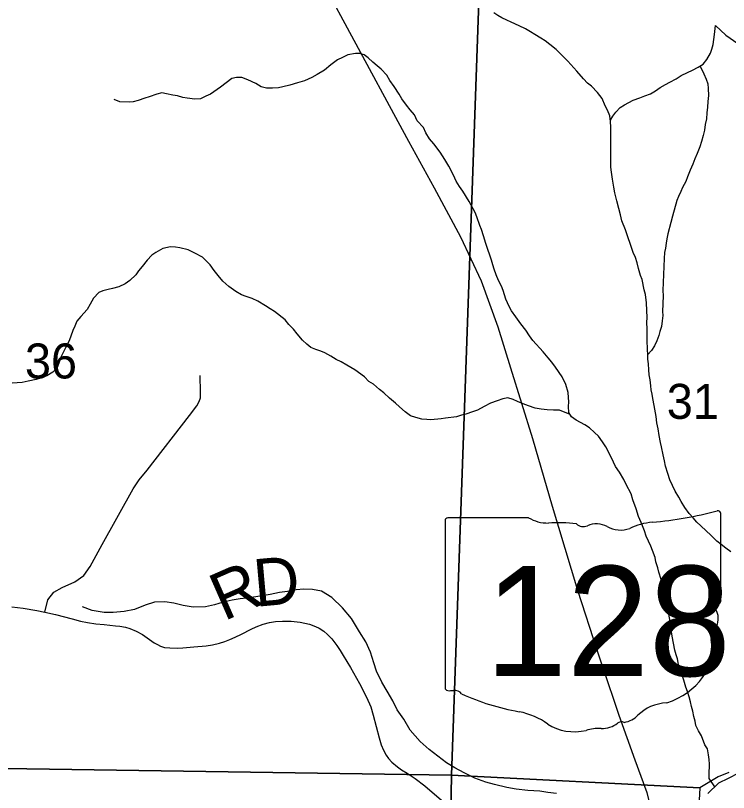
# Model space of a CAD drawing. Extents: x 0 to 34, y 0 to 22.
# Drawn here: x 3.401 to 4.254, y 17.776 to 18.706 of the extents above; entities that cross this region are included whole.
import ezdxf

# ---------------------------------------------------------------- set-up
doc = ezdxf.new("R2010")
doc.units = 0
for name, color, linetype in [('GM_X_County_Road', 7, 'Continuous'), ('GM_X_County_Road_Text', 7, 'Continuous'), ('GM_X_Major_River', 7, 'Continuous'), ('GM_X_Minor_River', 7, 'Continuous'), ('GM_X_Section', 7, 'Continuous'), ('GM_X_Section_Text', 7, 'Continuous'), ('GM_X_State_Location', 7, 'Continuous'), ('GM_X_State_Route', 7, 'Continuous'), ('GM_X_State_Shield', 7, 'Continuous'), ('GM_X_Township_Road', 7, 'Continuous')]:
    doc.layers.add(name, color=color, linetype=linetype)

msp = doc.modelspace()

# ---------------------------------------------------------------- linework, layer by layer
at = {"layer": 'GM_X_County_Road'}
msp.add_lwpolyline([(3.39721, 17.99822), (3.41074, 17.99624), (3.42685, 17.9937), (3.43662, 17.99179), (3.4494, 17.98866), (3.46903, 17.98358), (3.479, 17.98101), (3.48771, 17.97928), (3.49743, 17.97787), (3.50765, 17.97689), (3.52102, 17.97546), (3.52626, 17.97501), (3.53298, 17.97376), (3.53828, 17.97213), (3.5459, 17.96894), (3.5532, 17.96485), (3.56721, 17.95507), (3.57119, 17.95282), (3.57509, 17.95093), (3.57964, 17.94949), (3.58594, 17.94878), (3.59475, 17.94869), (3.60179, 17.94906), (3.61496, 17.95003), (3.6297, 17.9515), (3.63719, 17.95263), (3.6453, 17.95461), (3.65171, 17.95668), (3.65796, 17.95895), (3.66422, 17.96172), (3.67187, 17.96528), (3.68334, 17.97134), (3.68943, 17.97427), (3.69792, 17.97744), (3.70531, 17.97928), (3.71246, 17.98037), (3.72075, 17.981), (3.73119, 17.98076), (3.74219, 17.97969), (3.753, 17.97741), (3.76039, 17.97455), (3.76488, 17.97232), (3.77024, 17.96876), (3.77473, 17.96501), (3.77993, 17.95973), (3.78583, 17.95181), (3.78979, 17.94585), (3.79362, 17.93975), (3.80218, 17.92536), (3.81287, 17.9064), (3.8214, 17.88992), (3.82642, 17.8782), (3.82948, 17.86836), (3.83652, 17.84119), (3.83893, 17.83292), (3.8416, 17.82654), (3.84492, 17.82041), (3.84769, 17.81648), (3.85182, 17.81214), (3.8584, 17.80641), (3.86332, 17.80301), (3.87, 17.79882), (3.87945, 17.79246), (3.89098, 17.78361), (3.91371, 17.76432)], dxfattribs=at)
at = {"layer": 'GM_X_Major_River'}
msp.add_lwpolyline([(4.26631, 17.79912), (4.25396, 17.79266), (4.24239, 17.78694), (4.22985, 17.77441)], dxfattribs=at)
at = {"layer": 'GM_X_Minor_River'}
for points in [[(4.25715, 18.06375), (4.25122, 18.06814), (4.24568, 18.07251), (4.2405, 18.07649), (4.23317, 18.08396), (4.22765, 18.08909), (4.2214, 18.09501), (4.21661, 18.09935), (4.21223, 18.10445), (4.20749, 18.10993), (4.20242, 18.11694), (4.19774, 18.12432), (4.19487, 18.12936), (4.19056, 18.13635), (4.1842, 18.15025), (4.1818, 18.15756), (4.17907, 18.16639), (4.17777, 18.1729), (4.17613, 18.18017), (4.17418, 18.18974), (4.17321, 18.19472), (4.17161, 18.20313), (4.17036, 18.21116), (4.16872, 18.21843), (4.16783, 18.22569), (4.16563, 18.23906), (4.16403, 18.24748), (4.16306, 18.25245), (4.1621, 18.25781), (4.16152, 18.26277), (4.16062, 18.26964), (4.15969, 18.27575), (4.15914, 18.28185), (4.15863, 18.28909), (4.15806, 18.29443), (4.15785, 18.29938), (4.15773, 18.30698), (4.1573, 18.3165), (4.1572, 18.32448), (4.15704, 18.33095), (4.15692, 18.33855), (4.15712, 18.34424), (4.15665, 18.35262), (4.15621, 18.36176), (4.15504, 18.37206), (4.15371, 18.37742), (4.1511, 18.38968), (4.14937, 18.39468), (4.14663, 18.40313), (4.14533, 18.40964), (4.14328, 18.41617), (4.14046, 18.42235), (4.13737, 18.43196), (4.13388, 18.44081), (4.13114, 18.44927), (4.12695, 18.46006), (4.12531, 18.46733), (4.1233, 18.475), (4.12096, 18.48421), (4.11863, 18.49379), (4.11734, 18.50029), (4.11577, 18.50985), (4.11454, 18.51825), (4.11361, 18.52436), (4.11352, 18.53273), (4.11384, 18.54184), (4.1138, 18.55172), (4.11364, 18.55819), (4.11353, 18.56579), (4.11375, 18.57224), (4.11323, 18.5791), (4.11231, 18.5856), (4.10989, 18.59252), (4.10704, 18.59794), (4.10316, 18.60643), (4.09772, 18.61384), (4.09077, 18.6213), (4.08596, 18.62489), (4.0812, 18.62999), (4.07317, 18.63939), (4.06219, 18.65117), (4.05522, 18.65825), (4.04825, 18.66533), (4.04086, 18.67129), (4.03494, 18.67567), (4.03011, 18.67888), (4.02268, 18.68332), (4.01747, 18.68654), (4.01151, 18.68979), (4.00404, 18.69346), (3.99433, 18.69798), (3.9891, 18.70044), (3.98349, 18.70292), (3.97865, 18.70574), (3.97383, 18.70895)], [(4.23756, 18.68312), (4.23895, 18.69396), (4.25115, 18.68221), (4.26567, 18.67229), (4.28066, 18.66503), (4.29443, 18.65551), (4.30735, 18.6426), (4.31883, 18.63239), (4.32872, 18.61994), (4.33935, 18.60672), (4.3512, 18.59612), (4.35735, 18.5853), (4.36493, 18.57178)], [(4.11287, 18.58163), (4.11328, 18.58062), (4.1161, 18.58546), (4.11969, 18.59028), (4.12481, 18.5958), (4.13024, 18.59904), (4.13528, 18.6019), (4.1403, 18.60439), (4.14838, 18.60753), (4.15453, 18.6096), (4.16106, 18.61203), (4.16726, 18.61562), (4.17272, 18.61961), (4.17929, 18.62318), (4.18433, 18.62605), (4.19168, 18.62998), (4.19789, 18.63394), (4.2056, 18.63748), (4.2114, 18.64032), (4.21835, 18.64388), (4.22417, 18.64748), (4.22856, 18.65341), (4.23299, 18.66086), (4.23468, 18.66574), (4.236, 18.67101), (4.23697, 18.67706), (4.23756, 18.68312)], [(3.95151, 18.46992), (3.94438, 18.48309), (3.93645, 18.49552), (3.93248, 18.50136), (3.92852, 18.50758), (3.92535, 18.51491), (3.92003, 18.52573), (3.91499, 18.53351), (3.9096, 18.54243), (3.90196, 18.5522), (3.89685, 18.55808), (3.89255, 18.56545), (3.88974, 18.572), (3.88204, 18.57987), (3.87886, 18.58682), (3.87377, 18.59308), (3.8694, 18.59855), (3.86358, 18.60597), (3.86037, 18.61178), (3.8546, 18.62072), (3.84916, 18.62813), (3.84558, 18.63434), (3.839, 18.64178), (3.8342, 18.64575), (3.82904, 18.65011), (3.82352, 18.65524), (3.81871, 18.65883), (3.81345, 18.66053), (3.80813, 18.66034), (3.79897, 18.65875), (3.79278, 18.65554), (3.78661, 18.65272), (3.77881, 18.64691), (3.77099, 18.64034), (3.76247, 18.63531), (3.75589, 18.63174), (3.74702, 18.62786), (3.73895, 18.6251), (3.72975, 18.62238), (3.72133, 18.62039), (3.71598, 18.61944), (3.70875, 18.61893), (3.70153, 18.6188), (3.69552, 18.62053), (3.68882, 18.62456), (3.67948, 18.62906), (3.67236, 18.63159), (3.66591, 18.63181), (3.66017, 18.63049), (3.65354, 18.6254), (3.64652, 18.61994), (3.63484, 18.6116), (3.62907, 18.60952), (3.62289, 18.60632), (3.61604, 18.60579), (3.60696, 18.60687), (3.60168, 18.60781), (3.59528, 18.60955), (3.58962, 18.61051), (3.58209, 18.61229), (3.57643, 18.61325), (3.57067, 18.61154), (3.56145, 18.60844), (3.55609, 18.60711), (3.54801, 18.60397), (3.54227, 18.60265), (3.53732, 18.60206), (3.52632, 18.60244), (3.51959, 18.60533)], [(4.22055, 18.64524), (4.22492, 18.63605), (4.22774, 18.62987), (4.22982, 18.6241), (4.23, 18.61839), (4.23047, 18.61002), (4.22984, 18.60282), (4.22923, 18.596), (4.22863, 18.58956), (4.228, 18.58236), (4.22662, 18.57557), (4.22563, 18.56876), (4.22427, 18.56235), (4.22212, 18.5552), (4.22, 18.54881), (4.21706, 18.54055), (4.21418, 18.53419), (4.21168, 18.52782), (4.20878, 18.5207), (4.20547, 18.51283), (4.20338, 18.5072), (4.19934, 18.50012), (4.19727, 18.49525), (4.19478, 18.48926), (4.19272, 18.48439), (4.18751, 18.46557), (4.18535, 18.45804), (4.18185, 18.44448), (4.18088, 18.43843), (4.17995, 18.43353), (4.17898, 18.42748), (4.17804, 18.42219), (4.17741, 18.41499), (4.17608, 18.37665), (4.17624, 18.37019), (4.1756, 18.35159), (4.17581, 18.34664), (4.17522, 18.34058), (4.17422, 18.33377), (4.1725, 18.32775), (4.17119, 18.32286), (4.16869, 18.31648), (4.16582, 18.3105), (4.16221, 18.30492), (4.15784, 18.29998)], [(4.23812, 17.78267), (4.23145, 17.79254), (4.23124, 17.79749), (4.23166, 17.80964), (4.23148, 17.81534), (4.23052, 17.8207), (4.22925, 17.82796), (4.22601, 17.83301), (4.22221, 17.84378), (4.21861, 17.84961), (4.21541, 17.8558), (4.21446, 17.86115), (4.21314, 17.8669), (4.21183, 17.87302), (4.21013, 17.87878), (4.20917, 17.88414), (4.20749, 17.89027), (4.20544, 17.8968), (4.20333, 17.90182), (4.20097, 17.91026), (4.19858, 17.91794), (4.19651, 17.92409), (4.19478, 17.92909), (4.19349, 17.9356), (4.19177, 17.9406), (4.19045, 17.94635), (4.18882, 17.95438), (4.18722, 17.9628), (4.18567, 17.97311), (4.1851, 17.97845), (4.18288, 17.99107), (4.18229, 17.99603), (4.18102, 18.00329), (4.17798, 18.01404), (4.17497, 18.02592), (4.174, 18.0309), (4.17127, 18.03973), (4.16993, 18.04472), (4.16752, 18.05202), (4.16656, 18.05699), (4.16343, 18.06546), (4.1617, 18.07046), (4.15604, 18.08244), (4.15399, 18.08897), (4.15016, 18.09898), (4.147, 18.10631), (4.14389, 18.11516), (4.1401, 18.12631), (4.13806, 18.13322), (4.13199, 18.14446), (4.12917, 18.15063), (4.12415, 18.15917), (4.11945, 18.16617), (4.11697, 18.1712), (4.11129, 18.18279), (4.10773, 18.18938), (4.10377, 18.19559), (4.09906, 18.20222), (4.09427, 18.20656), (4.08802, 18.21248), (4.08244, 18.21571), (4.07722, 18.21855), (4.07238, 18.22138), (4.06683, 18.22537), (4.0636, 18.2308), (4.06308, 18.23766), (4.06327, 18.24336), (4.06308, 18.24868), (4.06253, 18.25478), (4.05982, 18.26438), (4.05558, 18.27326), (4.04763, 18.28494), (4.04327, 18.29079), (4.03853, 18.29628), (4.0327, 18.30332), (4.02025, 18.31667), (4.01627, 18.32251), (4.01195, 18.32912), (4.00614, 18.33692), (3.99997, 18.34511), (3.99491, 18.35251), (3.99205, 18.35755), (3.98818, 18.36642), (3.98474, 18.3768), (3.98302, 18.3818), (3.97946, 18.38877), (3.97665, 18.39532), (3.97423, 18.40225), (3.97251, 18.40725), (3.97081, 18.413), (3.96874, 18.41916), (3.96669, 18.42569), (3.96428, 18.43299), (3.96119, 18.44222), (3.95878, 18.44953), (3.95706, 18.45453), (3.95324, 18.46492), (3.95151, 18.46992)], [(4.06514, 18.22821), (4.0523, 18.23347), (4.04508, 18.23334), (4.03751, 18.23399), (4.03032, 18.23461), (4.02315, 18.236), (4.01527, 18.23855), (4.0089, 18.24105), (4.00217, 18.24395), (3.99694, 18.24641), (3.99054, 18.24815), (3.98444, 18.24722), (3.9779, 18.24478), (3.96982, 18.24164), (3.96209, 18.23773), (3.95435, 18.23344), (3.9482, 18.23137), (3.94013, 18.22861), (3.93517, 18.22764), (3.92902, 18.22557), (3.91605, 18.22374), (3.91071, 18.22316), (3.89853, 18.22206), (3.8936, 18.22224), (3.88754, 18.22282), (3.88039, 18.22459), (3.87401, 18.22671), (3.86772, 18.23149), (3.86071, 18.23743), (3.85592, 18.24178), (3.84892, 18.24772), (3.8423, 18.25403), (3.83712, 18.25801), (3.82976, 18.26473), (3.82418, 18.26796), (3.81905, 18.27346), (3.80757, 18.28183), (3.7979, 18.28749), (3.79119, 18.29114), (3.78521, 18.29401), (3.77852, 18.29804), (3.77145, 18.30208), (3.76658, 18.30415), (3.76058, 18.30626), (3.75496, 18.30835), (3.75016, 18.31232), (3.74463, 18.31707), (3.73845, 18.32489), (3.73408, 18.33036), (3.72857, 18.33587), (3.72422, 18.34172), (3.71128, 18.35167), (3.70607, 18.35489), (3.7005, 18.3585), (3.69119, 18.36377), (3.68447, 18.36704), (3.67735, 18.36957), (3.67172, 18.37166), (3.66503, 18.37569), (3.6565, 18.38169), (3.64951, 18.38801), (3.64404, 18.39466), (3.63893, 18.40054), (3.63424, 18.40754), (3.62506, 18.4166), (3.61612, 18.42147), (3.60791, 18.42556), (3.59811, 18.42779), (3.59283, 18.42874), (3.58676, 18.42895), (3.57758, 18.42698), (3.56945, 18.42232), (3.5644, 18.41908), (3.55888, 18.41319), (3.55292, 18.40542), (3.54856, 18.40024), (3.54536, 18.39542), (3.5383, 18.38882), (3.53246, 18.38484), (3.52513, 18.38129), (3.51746, 18.37928), (3.5121, 18.37794), (3.50597, 18.37626), (3.50096, 18.37415), (3.49466, 18.36753), (3.49062, 18.36044), (3.48698, 18.35411), (3.47947, 18.34563), (3.47473, 18.34009), (3.47224, 18.3341), (3.47016, 18.32885), (3.46556, 18.31647), (3.46108, 18.30788), (3.45577, 18.29704), (3.45324, 18.28953), (3.45117, 18.28466), (3.44604, 18.27914), (3.43905, 18.27444), (3.43251, 18.27201), (3.42599, 18.27033), (3.41642, 18.268)], [(3.41642, 18.268), (3.40955, 18.26672), (3.39736, 18.26562)], [(4.04866, 17.77454), (4.03845, 17.77597), (4.02861, 17.77739), (4.0142, 17.77818), (4.00057, 17.77971), (3.98924, 17.78193), (3.97453, 17.78539), (3.96397, 17.78797), (3.95082, 17.79291), (3.9381, 17.79935), (3.92725, 17.80536), (3.91717, 17.81135), (3.89636, 17.82715), (3.88563, 17.83696), (3.87348, 17.85023), (3.8659, 17.86375), (3.85823, 17.87461), (3.85285, 17.88541), (3.84597, 17.89701), (3.83983, 17.90782), (3.83337, 17.92093), (3.83024, 17.93091), (3.82606, 17.94395), (3.82072, 17.95627), (3.81309, 17.96827), (3.80329, 17.98413), (3.79265, 17.99698), (3.78009, 18.00912), (3.76739, 18.01671), (3.75682, 18.01891), (3.74658, 18.0192), (3.73706, 18.01833), (3.72674, 18.01635), (3.71721, 18.01509), (3.70613, 18.01275), (3.69392, 18.01082), (3.68133, 18.0089), (3.67028, 18.00769), (3.66074, 18.00606), (3.65004, 18.00371), (3.63931, 18.00059), (3.6286, 17.99786), (3.61416, 17.99751), (3.60207, 17.99975), (3.59075, 18.00236), (3.58017, 18.00418), (3.56762, 18.00378), (3.5565, 17.99991), (3.54382, 17.99495), (3.5316, 17.99264), (3.51826, 17.99112), (3.50763, 17.99142), (3.49327, 17.99374), (3.48162, 17.99787)]]:
    msp.add_lwpolyline(points, dxfattribs=at)
at = {"layer": 'GM_X_Section'}
for points in [[(2.96714, 18.80963), (3.9584, 18.80223), (3.92299, 17.79649), (2.93343, 17.81142)], [(3.92299, 17.79649), (3.90541, 16.80662), (2.90066, 16.8204), (2.93343, 17.81142)]]:
    msp.add_lwpolyline(points, close=True, dxfattribs=at)
for points in [[(4.25494, 17.7998), (4.24193, 17.79444), (4.22001, 17.78133), (3.92299, 17.79649), (3.9584, 18.80223), (4.13395, 18.79266), (4.22627, 18.75671), (4.30272, 18.73818)], [(3.90541, 16.80662), (3.92299, 17.79649), (4.22001, 17.78133), (4.21928, 17.76658)]]:
    msp.add_lwpolyline(points, dxfattribs=at)
at = {"layer": 'GM_X_State_Route'}
for points in [[(3.8721, 18.55519), (3.85915, 18.57872), (3.76419, 18.75474), (3.70539, 18.85908), (3.67386, 18.91588), (3.66486, 18.93239), (3.64134, 18.98043), (3.61281, 19.04149), (3.54577, 19.2539), (3.47803, 19.46696), (3.44542, 19.57897), (3.44165, 19.62804), (3.44885, 19.67609), (3.46345, 19.71601), (3.49295, 19.76127), (3.49665, 19.7654), (3.53657, 19.81001), (3.63324, 19.90612)], [(4.11938, 17.88105), (4.09759, 17.94507), (4.07433, 18.01763), (4.04393, 18.11796), (4.02041, 18.19903), (3.99414, 18.28385), (3.97874, 18.33301), (3.95885, 18.38781), (3.93433, 18.4406), (3.90281, 18.4994), (3.8721, 18.55519)], [(4.17478, 17.68954), (4.17396, 17.70876), (4.16653, 17.73952), (4.15715, 17.77554), (4.14276, 17.81458), (4.12387, 17.86788), (4.11938, 17.88105)]]:
    msp.add_lwpolyline(points, dxfattribs=at)
at = {"layer": 'GM_X_State_Shield'}
for p, q in [((4.24516, 18.00499), (4.24516, 18.10968)), ((3.91557, 18.10127), (3.91557, 17.90115)), ((4.01534, 18.10472), (3.91882, 18.10472)), ((4.24512, 18.00502), (4.24516, 18.00499))]:
    msp.add_line(p, q, dxfattribs=at)
for centre, major_axis, start_param, end_param in [((4.12775, 18.37755), (0.34952, 0), 4.814394, 5.042369), ((4.2415, 18.11011), (0.00367, 0), 6.141152, 7.989035), ((3.91935, 18.1017), (0.00382, 0), 1.712693, 3.28349), ((4.03832, 18.12795), (0.03703, 0), 4.042523, 4.731795), ((4.0506, 17.99237), (0.13295, 0), 1.404758, 1.657858), ((4.09647, 18.07961), (0.02221, 0), 0.950623, 2.079405), ((4.17234, 18.04359), (0.07032, 0), 1.699011, 2.107814), ((4.08079, 18.10274), (0.01068, 0), 3.836095, 5.185415), ((4.12514, 18.11133), (0.02672, 0), 4.081561, 5.145723), ((4.24431, 17.99731), (0.00568, 0), 1.883978, 3.671073), ((4.24124, 18.00459), (0.00393, 0), 5.05454, 6.418171), ((4.20818, 17.98407), (0.03409, 0), 5.934695, 6.695948), ((4.2583, 17.96118), (0.0248, 0), 2.387724, 3.262537), ((4.14733, 17.94786), (0.08742, 0), 5.101752, 6.440018), ((3.91938, 17.90072), (0.00385, 0), 3.00124, 4.508301), ((3.91997, 17.92119), (0.0294, 0), 4.665946, 4.897461), ((3.92598, 17.88961), (0.0106, 0), 0.519207, 1.627899), ((4.05981, 18.06941), (0.2524, 0), 4.195997, 4.488961), ((4.18419, 17.84497), (0.04788, 0), 1.647645, 2.488434), ((3.98456, 17.81125), (0.07897, 0), 0.823519, 1.323587), ((4.12353, 17.88176), (0.02824, 0), 4.937069, 5.64225), ((4.06997, 17.88861), (0.05011, 0), 4.026481, 4.996735), ((4.10258, 17.87363), (0.0267, 0), 4.691044, 5.507374), ((4.12674, 17.85425), (0.00752, 0), 1.147584, 2.315152), ((4.09892, 17.81943), (0.04118, 0), 1.495662, 1.94098)]:
    msp.add_ellipse(centre, major_axis=major_axis, ratio=0.8, start_param=start_param, end_param=end_param, dxfattribs=at)
at = {"layer": 'GM_X_Township_Road'}
msp.add_lwpolyline([(3.43662, 17.99179), (3.44006, 18.00654), (3.44713, 18.01542), (3.45732, 18.02134), (3.47228, 18.02803), (3.48334, 18.03552), (3.49069, 18.04618), (3.50514, 18.07246), (3.54231, 18.13925), (3.54954, 18.15026), (3.55913, 18.16174), (3.60957, 18.22698), (3.61845, 18.23858), (3.62117, 18.24403), (3.62259, 18.24806), (3.62271, 18.25504), (3.62248, 18.27479)], dxfattribs=at)

# ---------------------------------------------------------------- texts
at = {"layer": 'GM_X_County_Road_Text'}
for s, rotation, p in [('D', 5.11396, (3.6887, 17.99801)), ('R', 23.63318, (3.65063, 17.9805))]:
    msp.add_text(s, height=0.05682, rotation=rotation, dxfattribs=at).set_placement(p)
at = {"layer": 'GM_X_Section_Text'}
for s, p in [('36', (3.41272, 18.2714)), ('31', (4.18064, 18.22307))]:
    msp.add_text(s, height=0.041856, rotation=0.00001, dxfattribs=at).set_placement(p)
at = {"layer": 'GM_X_State_Location'}
for s, p in [('s', (4.07666, 17.98791)), ('r', (4.07665, 17.98791))]:
    msp.add_text(s, height=0.000189, dxfattribs=at).set_placement(p)
msp.add_text('128', height=0.000189, rotation=0.00001, dxfattribs=at).set_placement((4.0098, 17.97413))
at = {"layer": 'GM_X_State_Shield'}
msp.add_text('128', height=0.131836, dxfattribs=at).set_placement((3.96319, 17.91527))

doc.saveas('drawing.dxf')
